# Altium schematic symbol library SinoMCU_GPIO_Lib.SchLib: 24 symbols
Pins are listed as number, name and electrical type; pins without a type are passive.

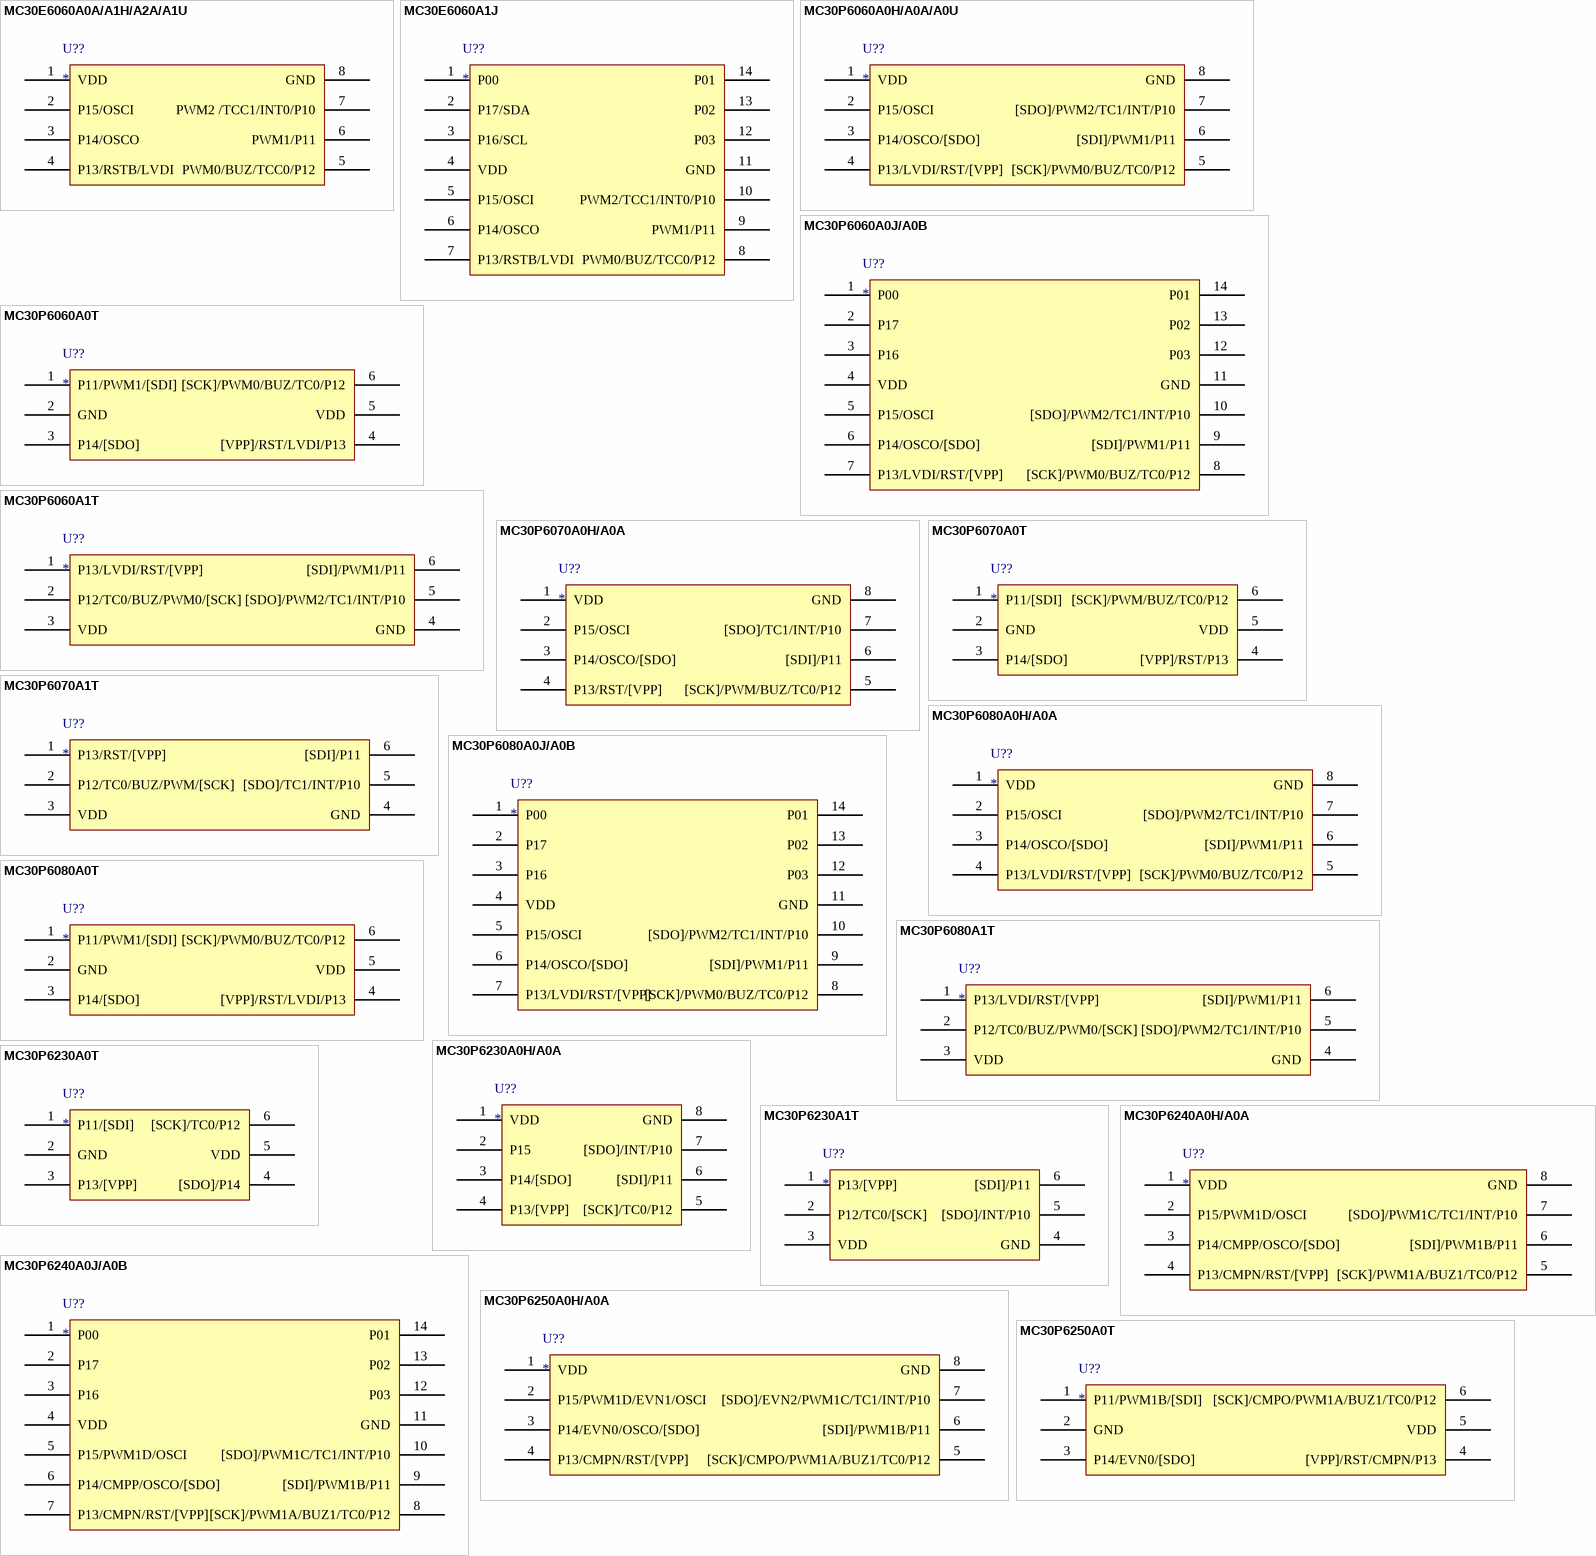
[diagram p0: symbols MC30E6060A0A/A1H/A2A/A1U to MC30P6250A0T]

## MC30E6060A0A/A1H/A2A/A1U
designator U??
pins: 1 VDD, 2 P15/OSCI, 3 P14/OSCO, 4 P13/RSTB/LVDI, 5 PWM0/BUZ/TCC0/P12, 6 PWM1/P11, 7 PWM2 /TCC1/INT0/P10, 8 GND

## MC30E6060A1J
designator U??
pins: 1 P00, 2 P17/SDA, 3 P16/SCL, 4 VDD, 5 P15/OSCI, 6 P14/OSCO, 7 P13/RSTB/LVDI, 8 PWM0/BUZ/TCC0/P12, 9 PWM1/P11, 10 PWM2/TCC1/INT0/P10, 11 GND, 12 P03, 13 P02, 14 P01

## MC30P6060A0H/A0A/A0U
designator U??
pins: 1 VDD, 2 P15/OSCI, 3 P14/OSCO/[SDO], 4 P13/LVDI/RST/[VPP], 5 [SCK]/PWM0/BUZ/TC0/P12, 6 [SDI]/PWM1/P11, 7 [SDO]/PWM2/TC1/INT/P10, 8 GND

## MC30P6060A0J/A0B
designator U??
pins: 1 P00, 2 P17, 3 P16, 4 VDD, 5 P15/OSCI, 6 P14/OSCO/[SDO], 7 P13/LVDI/RST/[VPP], 8 [SCK]/PWM0/BUZ/TC0/P12, 9 [SDI]/PWM1/P11, 10 [SDO]/PWM2/TC1/INT/P10, 11 GND, 12 P03, 13 P02, 14 P01

## MC30P6060A0T
designator U??
pins: 1 P11/PWM1/[SDI], 2 GND , 3 P14/[SDO], 4 [VPP]/RST/LVDI/P13, 5 VDD, 6 [SCK]/PWM0/BUZ/TC0/P12

## MC30P6060A1T
designator U??
pins: 1 P13/LVDI/RST/[VPP], 2 P12/TC0/BUZ/PWM0/[SCK], 3 VDD, 4 GND, 5 [SDO]/PWM2/TC1/INT/P10, 6 [SDI]/PWM1/P11

## MC30P6070A0H/A0A
designator U??
pins: 1 VDD, 2 P15/OSCI, 3 P14/OSCO/[SDO], 4 P13/RST/[VPP], 5 [SCK]/PWM/BUZ/TC0/P12, 6 [SDI]/P11, 7 [SDO]/TC1/INT/P10, 8 GND

## MC30P6070A0T
designator U??
pins: 1 P11/[SDI], 2 GND, 3 P14/[SDO], 4 [VPP]/RST/P13, 5 VDD, 6 [SCK]/PWM/BUZ/TC0/P12

## MC30P6070A1T
designator U??
pins: 1 P13/RST/[VPP], 2 P12/TC0/BUZ/PWM/[SCK], 3 VDD, 4 GND, 5 [SDO]/TC1/INT/P10, 6 [SDI]/P11

## MC30P6080A0H/A0A
designator U??
pins: 1 VDD, 2 P15/OSCI, 3 P14/OSCO/[SDO], 4 P13/LVDI/RST/[VPP], 5 [SCK]/PWM0/BUZ/TC0/P12, 6 [SDI]/PWM1/P11, 7 [SDO]/PWM2/TC1/INT/P10, 8 GND

## MC30P6080A0J/A0B
designator U??
pins: 1 P00, 2 P17 , 3 P16, 4 VDD, 5 P15/OSCI, 6 P14/OSCO/[SDO], 7 P13/LVDI/RST/[VPP], 8 [SCK]/PWM0/BUZ/TC0/P12, 9 [SDI]/PWM1/P11, 10 [SDO]/PWM2/TC1/INT/P10, 11 GND, 12 P03, 13 P02, 14 P01

## MC30P6080A0T
designator U??
pins: 1 P11/PWM1/[SDI], 2 GND, 3 P14/[SDO], 4 [VPP]/RST/LVDI/P13, 5 VDD, 6 [SCK]/PWM0/BUZ/TC0/P12

## MC30P6080A1T
designator U??
pins: 1 P13/LVDI/RST/[VPP], 2 P12/TC0/BUZ/PWM0/[SCK], 3 VDD, 4 GND, 5 [SDO]/PWM2/TC1/INT/P10, 6 [SDI]/PWM1/P11

## MC30P6230A0H/A0A
designator U??
pins: 1 VDD, 2 P15, 3 P14/[SDO], 4 P13/[VPP], 5 [SCK]/TC0/P12, 6 [SDI]/P11, 7 [SDO]/INT/P10, 8 GND

## MC30P6230A0T
designator U??
pins: 1 P11/[SDI], 2 GND, 3 P13/[VPP], 4 [SDO]/P14, 5 VDD, 6 [SCK]/TC0/P12

## MC30P6230A1T
designator U??
pins: 1 P13/[VPP] , 2 P12/TC0/[SCK], 3 VDD, 4 GND, 5 [SDO]/INT/P10, 6 [SDI]/P11

## MC30P6240A0H/A0A
designator U??
pins: 1 VDD, 2 P15/PWM1D/OSCI, 3 P14/CMPP/OSCO/[SDO], 4 P13/CMPN/RST/[VPP], 5 [SCK]/PWM1A/BUZ1/TC0/P12, 6 [SDI]/PWM1B/P11, 7 [SDO]/PWM1C/TC1/INT/P10, 8 GND

## MC30P6240A0J/A0B
designator U??
pins: 1 P00, 2 P17, 3 P16, 4 VDD, 5 P15/PWM1D/OSCI, 6 P14/CMPP/OSCO/[SDO], 7 P13/CMPN/RST/[VPP], 8 [SCK]/PWM1A/BUZ1/TC0/P12, 9 [SDI]/PWM1B/P11, 10 [SDO]/PWM1C/TC1/INT/P10, 11 GND, 12 P03, 13 P02, 14 P01

## MC30P6250A0H/A0A
designator U??
pins: 1 VDD, 2 P15/PWM1D/EVN1/OSCI, 3 P14/EVN0/OSCO/[SDO], 4 P13/CMPN/RST/[VPP], 5 [SCK]/CMPO/PWM1A/BUZ1/TC0/P12, 6 [SDI]/PWM1B/P11, 7 [SDO]/EVN2/PWM1C/TC1/INT/P10, 8 GND

## MC30P6250A0T
designator U??
pins: 1 P11/PWM1B/[SDI], 2 GND, 3 P14/EVN0/[SDO], 4 [VPP]/RST/CMPN/P13, 5 VDD, 6 [SCK]/CMPO/PWM1A/BUZ1/TC0/P12

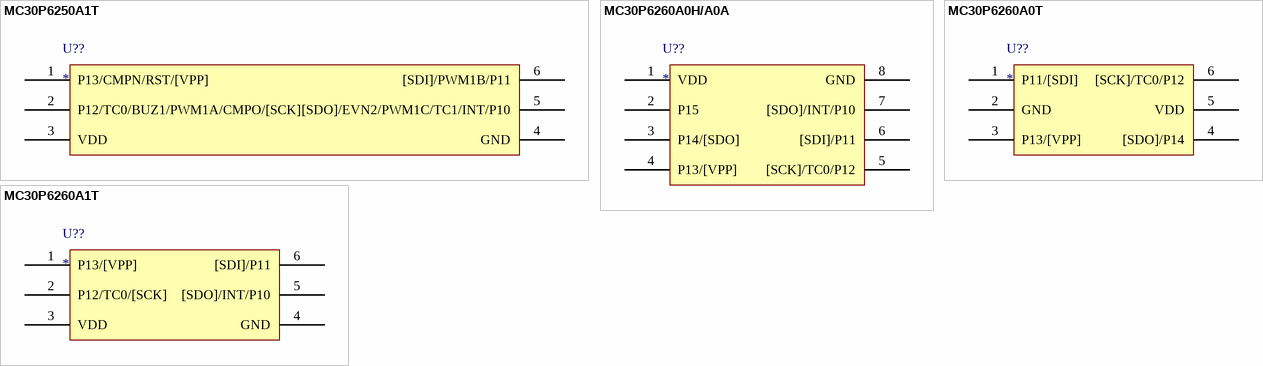
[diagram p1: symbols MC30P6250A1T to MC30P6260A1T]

## MC30P6250A1T
designator U??
pins: 1 P13/CMPN/RST/[VPP], 2 P12/TC0/BUZ1/PWM1A/CMPO/[SCK], 3 VDD, 4 GND, 5 [SDO]/EVN2/PWM1C/TC1/INT/P10, 6 [SDI]/PWM1B/P11

## MC30P6260A0H/A0A
designator U??
pins: 1 VDD, 2 P15, 3 P14/[SDO], 4 P13/[VPP], 5 [SCK]/TC0/P12, 6 [SDI]/P11, 7 [SDO]/INT/P10, 8 GND

## MC30P6260A0T
designator U??
pins: 1 P11/[SDI], 2 GND, 3 P13/[VPP], 4 [SDO]/P14, 5 VDD, 6 [SCK]/TC0/P12

## MC30P6260A1T
designator U??
pins: 1 P13/[VPP], 2 P12/TC0/[SCK], 3 VDD, 4 GND, 5 [SDO]/INT/P10, 6 [SDI]/P11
